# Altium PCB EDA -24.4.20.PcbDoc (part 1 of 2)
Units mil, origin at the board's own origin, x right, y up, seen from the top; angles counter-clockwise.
Board outline 1259.84 x 1062.87 mil, 4 copper layers (Top1, Gnd2, Signal3, Bottom4), stack 30.634 mil thick; 95 components, 111 nets, 499 pads, 259 vias.
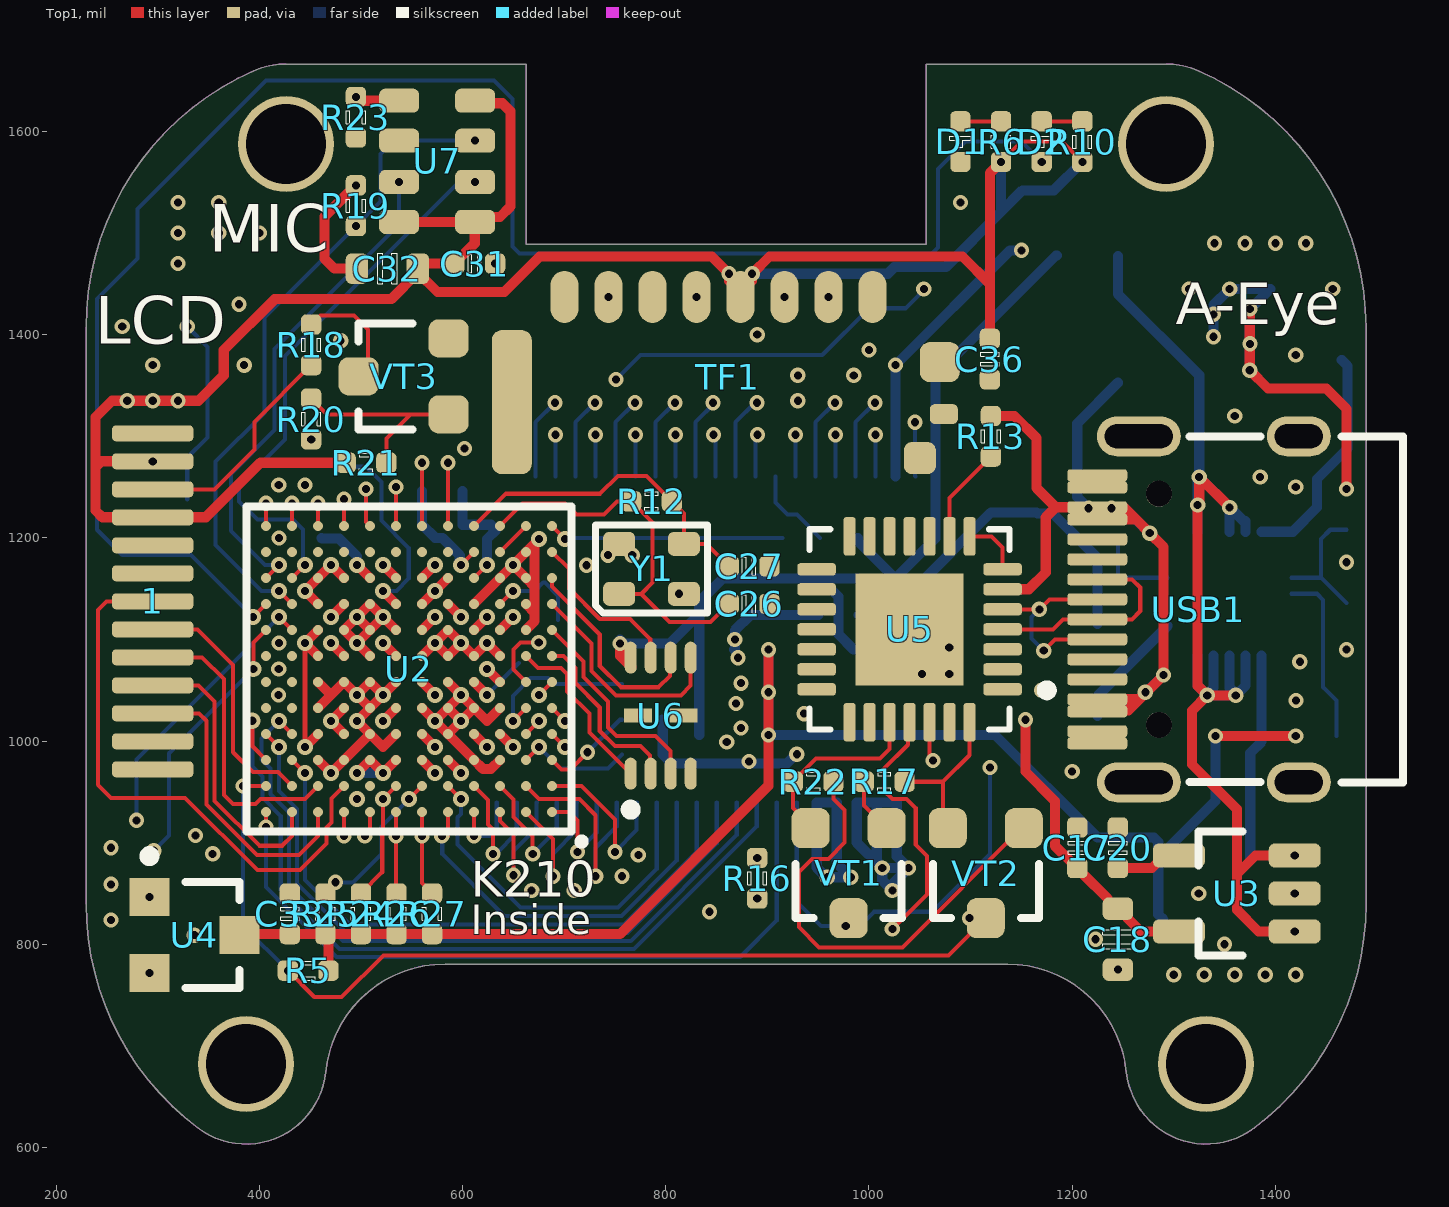
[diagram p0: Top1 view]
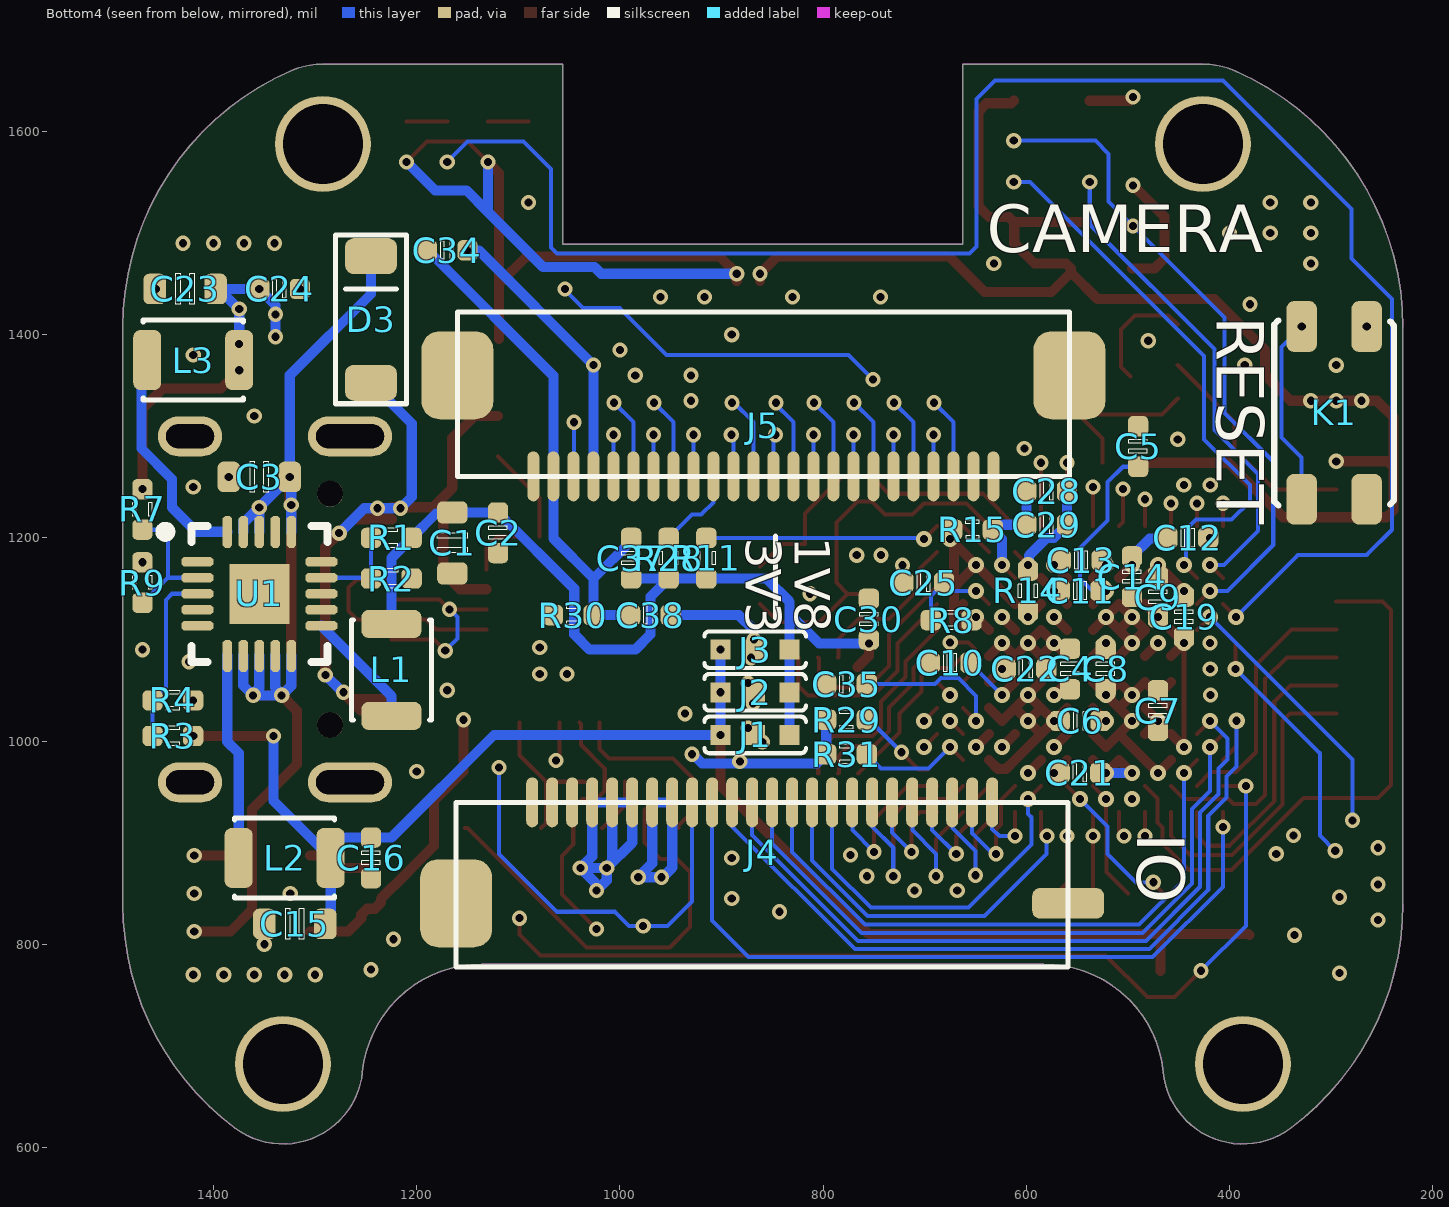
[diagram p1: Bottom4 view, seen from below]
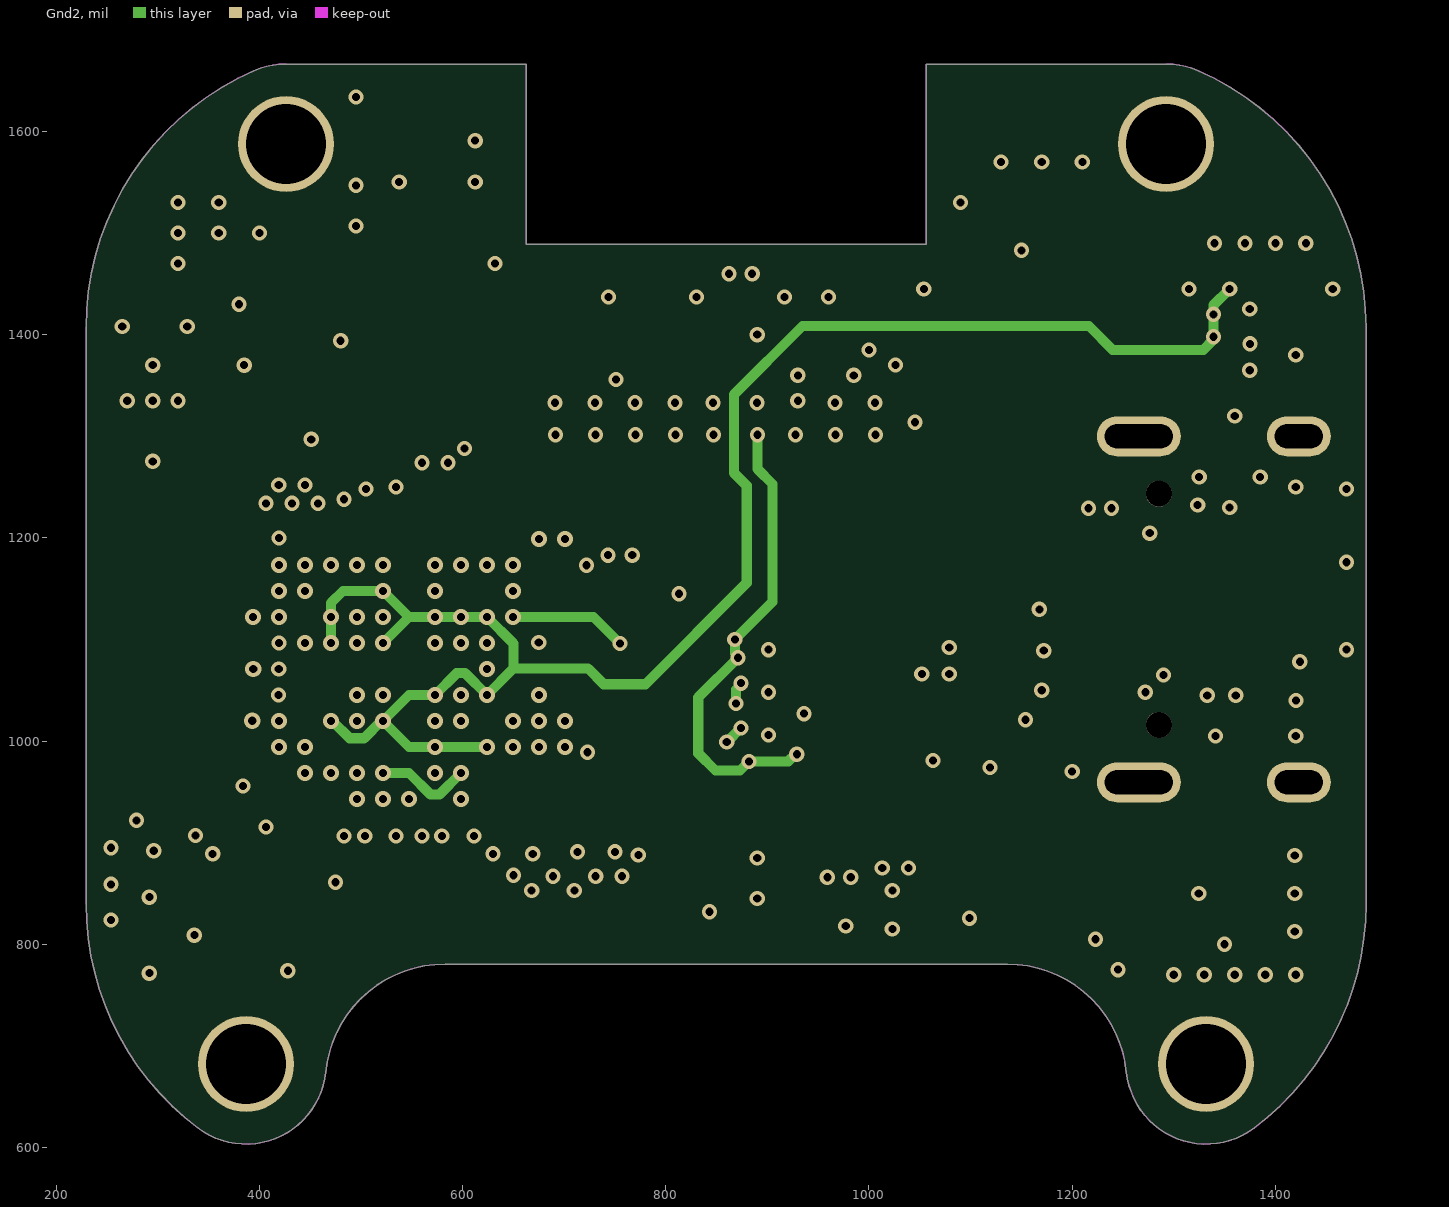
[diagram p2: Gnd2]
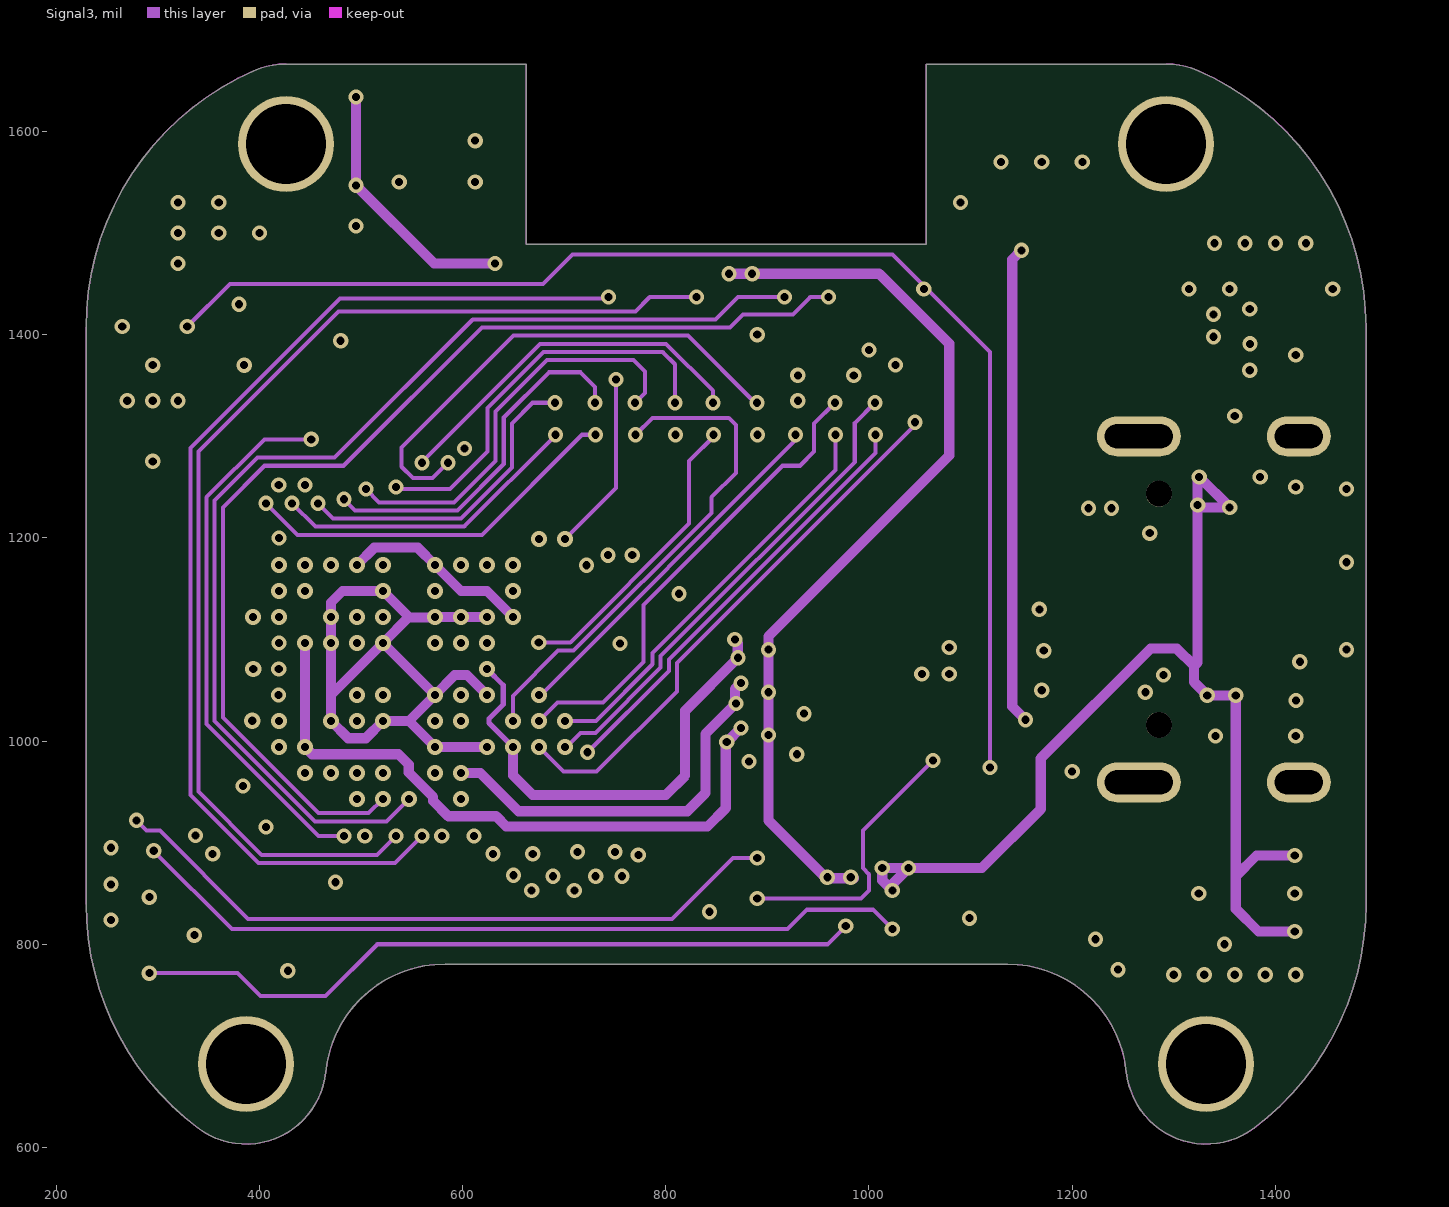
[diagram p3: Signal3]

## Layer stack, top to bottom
Top Solder: solder mask 0.4, Solder Resist, Dk 3.5
Top1: signal copper 1.4
Dielectric1: core 10, FR-4, Dk 4.2
Gnd2: signal copper 1.417
Dielectric3: core 10, Dk 4.2
Signal3: signal copper 1.417
Dielectric2: prepreg 5, Dk 4.2
Bottom4: signal copper 1.4
Bottom Solder: solder mask 0.4, Solder Resist, Dk 3.5

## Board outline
339.65,619.1 ccw(c386.9,682.09) 465.24,674.22 cw(c582.76,662.41) 582.76,780.52 1135.92,780.52 cw(c1135.92,662.41) 1253.43,674.22 ccw(c1331.78,682.09) 1379.02,619.1 ccw(c1213.67,839.57) 1489.26,839.57 1489.26,1407.19 ccw(c1213.67,1407.19) 1323.9,1659.77 ccw(c1292.41,1587.61) 1292.41,1666.35 1056.19,1666.35 1056.19,1489.18 662.49,1489.18 662.49,1666.35 426.27,1666.35 ccw(c426.27,1587.61) 394.77,1659.77 ccw(c505.01,1407.19) 229.42,1407.19 229.42,839.57 ccw(c505.01,839.57)

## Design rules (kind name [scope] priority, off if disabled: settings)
AssemblyTestPointUsage [All] p0: scope1count=1 scope1_0_kind=Board scope1_0_value=Board scope2count=1 scope2_0_kind=Board scope2_0_value=Board commentlength=0
AssemblyTestpoint [All] p0: scope1count=1 scope1_0_kind=Board scope1_0_value=Board scope2count=1 scope2_0_kind=Board scope2_0_value=Board commentlength=0
Clearance Solder_Clearance [All] p0: scope1count=1 scope1_0_kind=Layer scope1_0_value=TOP scope2count=1 scope2_0_kind=Layer scope2_0_value=TOP commentlength=0 gap=4
Clearance [All] p0: scope1count=1 scope1_0_kind=Board scope1_0_value=Board scope2count=1 scope2_0_kind=Board scope2_0_value=Board commentlength=0 gap=4
Clearance Solder_Clearance [OnLayer('Top Solder') vs OnLayer('Top Solder')] p1: gap=4 ignorepadtopadclearanceinfootprint=FALSE except(0: Arc-Hole Track-Hole SMDPad-Hole THPad-Hole Via-Hole Fill-Hole Poly-Hole Region-Hole Text-Hole)
Clearance [All] p2: gap=4 ignorepadtopadclearanceinfootprint=FALSE except(0: Arc-Hole Track-Hole SMDPad-Hole THPad-Hole Via-Hole Fill-Hole Poly-Hole Region-Hole Text-Hole)
ComponentClearance [All] p0: scope1count=1 scope1_0_kind=Board scope1_0_value=Board scope2count=1 scope2_0_kind=Board scope2_0_value=Board commentlength=0 gap=0 collisioncheckmode=3
ComponentClearance [All] p1: gap=0 collisioncheckmode=3 verticalgap=0 showdistances=FALSE
DiffPairsRouting [All] p0: scope1count=1 scope1_0_kind=Board scope1_0_value=Board scope2count=1 scope2_0_kind=Board scope2_0_value=Board commentlength=0
DiffPairsRouting [All] p1: maxlimit=9 minlimit=9 mostfreqgap=9 toplayer_minwidth=15 toplayer_maxwidth=15 toplayer_prefwidth=15 midlayer1_minwidth=15 midlayer1_maxwidth=15 midlayer1_prefwidth=15 midlayer2_minwidth=15 midlayer2_maxwidth=15 midlayer2_prefwidth=15 bottomlayer_minwidth=15 bottomlayer_maxwidth=15 bottomlayer_prefwidth=15 maxuncoupledlength=500
FabricationTestPointUsage [All] p0: scope1count=1 scope1_0_kind=Board scope1_0_value=Board scope2count=1 scope2_0_kind=Board scope2_0_value=Board commentlength=0 valid=0 allowmultiple=FALSE
FabricationTestpoint [All] p0: scope1count=1 scope1_0_kind=Board scope1_0_value=Board scope2count=1 scope2_0_kind=Board scope2_0_value=Board commentlength=0 side=3 testpointundercomponent=TRUE minsize=40 maxsize=100 preferedsize=60 minholesize=0 maxholesize=40 preferedholesize=32 testpointgrid=1
FanoutControl Fanout_BGA [All] p0: scope1count=1 scope1_0_kind=Board scope1_0_value=Board scope2count=1 scope2_0_kind=Board scope2_0_value=Board commentlength=26 // Fanout_BGA (Default Rule)
FanoutControl Fanout_LCC [All] p0 off: scope1count=1 scope1_0_kind=Board scope1_0_value=Board scope2count=1 scope2_0_kind=Board scope2_0_value=Board commentlength=69 // Protel DXP Scope 1 Expression Was: IsLCC   Fanout_LCC (Default Rule)
FanoutControl Fanout_SOIC [All] p0 off: scope1count=1 scope1_0_kind=Board scope1_0_value=Board scope2count=1 scope2_0_kind=Board scope2_0_value=Board commentlength=71 // Protel DXP Scope 1 Expression Was: IsSOIC   Fanout_SOIC (Default Rule)
FanoutControl Fanout_Small [All] p0 off: scope1count=1 scope1_0_kind=Board scope1_0_value=Board scope2count=1 scope2_0_kind=Board scope2_0_value=Board commentlength=84 // Protel DXP Scope 1 Expression Was: (CompPinCount < 5)   Fanout_Small (Default Rule)
FanoutControl Fanout_Default [All] p0: scope1count=1 scope1_0_kind=Board scope1_0_value=Board scope2count=1 scope2_0_kind=Board scope2_0_value=Board commentlength=30 // Fanout_Default (Default Rule)
FanoutControl Fanout_BGA [All] p1: bgadir=Out bgaviamode=Centered fanoutstyle=Auto fanoutdirection=Alternating viagrid=1 // Fanout_BGA (Default Rule)
Height [All] p0: scope1count=1 scope1_0_kind=Board scope1_0_value=Board scope2count=1 scope2_0_kind=Board scope2_0_value=Board commentlength=0
HoleSize [All] p0: scope1count=1 scope1_0_kind=Board scope1_0_value=Board scope2count=1 scope2_0_kind=Board scope2_0_value=Board commentlength=0 absolutevalues=TRUE maxlimit=10000 minlimit=8 maxpercent=80.000 minpercent=20.000
HoleSize [All] p1: absolutevalues=TRUE maxlimit=10000 minlimit=8 maxpercent=80.000 minpercent=20.000
HoleToHoleClearance [All] p0: scope1count=1 scope1_0_kind=Board scope1_0_value=Board scope2count=1 scope2_0_kind=Board scope2_0_value=Board commentlength=0
LayerPairs [All] p0: scope1count=1 scope1_0_kind=Board scope1_0_value=Board scope2count=1 scope2_0_kind=Board scope2_0_value=Board commentlength=0 enforce=TRUE
MinimumSolderMaskSliver [All] p0 off: scope1count=1 scope1_0_kind=Board scope1_0_value=Board scope2count=1 scope2_0_kind=Board scope2_0_value=Board commentlength=0
MinimumSolderMaskSliver [All] p1 off: minsoldermaskwidth=2
NetAntennae [All] p0: scope1count=1 scope1_0_kind=Board scope1_0_value=Board scope2count=1 scope2_0_kind=Board scope2_0_value=Board commentlength=0
PasteMaskExpansion [All] p0: scope1count=1 scope1_0_kind=Board scope1_0_value=Board scope2count=1 scope2_0_kind=Board scope2_0_value=Board commentlength=0 expansion=0
PlaneClearance [All] p0: scope1count=1 scope1_0_kind=Board scope1_0_value=Board scope2count=1 scope2_0_kind=Board scope2_0_value=Board commentlength=0 clearance=8
PlaneClearance [All] p1: clearance=8
PlaneConnect [All] p0: scope1count=1 scope1_0_kind=Board scope1_0_value=Board scope2count=1 scope2_0_kind=Board scope2_0_value=Board commentlength=0 planeconnectstyle=Direct reliefexpansion=20 reliefentries=4 reliefconductorwidth=10 reliefairgap=10
PlaneConnect [All] p1: planeconnectstyle=Direct reliefexpansion=20 reliefentries=4 reliefconductorwidth=10 reliefairgap=10
PolygonConnect [All] p0: scope1count=1 scope1_0_kind=Board scope1_0_value=Board scope2count=1 scope2_0_kind=Board scope2_0_value=Board commentlength=0 connectstyle=Direct reliefconductorwidth=10 reliefentries=4 polygonreliefangle="90 Angle"
PolygonConnect [All] p1: connectstyle=Direct reliefconductorwidth=10 reliefentries=4 polygonreliefangle="90 Angle" airgapwidth=10
RoutingCorners [All] p0: scope1count=1 scope1_0_kind=Board scope1_0_value=Board scope2count=1 scope2_0_kind=Board scope2_0_value=Board commentlength=0 cornerstyle=45-Degree minsetback=100 maxsetback=100
RoutingLayers [All] p0: scope1count=1 scope1_0_kind=Board scope1_0_value=Board scope2count=1 scope2_0_kind=Board scope2_0_value=Board commentlength=0 top layer=Automatic mid layer 1=Automatic mid layer 2=Automatic bottom layer=Automatic
RoutingPriority [All] p0: scope1count=1 scope1_0_kind=Board scope1_0_value=Board scope2count=1 scope2_0_kind=Board scope2_0_value=Board commentlength=0
RoutingTopology [All] p0: scope1count=1 scope1_0_kind=Board scope1_0_value=Board scope2count=1 scope2_0_kind=Board scope2_0_value=Board commentlength=0 topology=Shortest
RoutingVias [All] p0: scope1count=1 scope1_0_kind=Board scope1_0_value=Board scope2count=1 scope2_0_kind=Board scope2_0_value=Board commentlength=0 holewidth=8 width=16 viastyle="Through Hole" minholewidth=6 minwidth=12 maxholewidth=28 maxwidth=50
RoutingVias [All] p1: holewidth=8 width=16 viastyle="Through Hole" minholewidth=6 minwidth=12 maxholewidth=28 maxwidth=50
ShortCircuit [All] p0: scope1count=1 scope1_0_kind=Board scope1_0_value=Board scope2count=1 scope2_0_kind=Board scope2_0_value=Board commentlength=0 allowed=FALSE
SilkToBoardRegionClearance [All] p0: scope1count=1 scope1_0_kind=Board scope1_0_value=Board scope2count=1 scope2_0_kind=Board scope2_0_value=Board commentlength=0
SilkToSilkClearance [All] p0: scope1count=1 scope1_0_kind=Board scope1_0_value=Board scope2count=1 scope2_0_kind=Board scope2_0_value=Board commentlength=0
SilkToSilkClearance [All] p1: silktosilkclearance=0
SilkToSolderMaskClearance [All] p0 off: scope1count=1 scope1_0_kind=Board scope1_0_value=Board scope2count=1 scope2_0_kind=Board scope2_0_value=Board commentlength=44 // Protel DXP Scope 1 Expression Was: IsPad
SilkToSolderMaskClearance [IsPad] p1: minsilkscreentomaskgap=0 clearancetoexposedcopper=TRUE
SolderMaskExpansion [All] p0: scope1count=1 scope1_0_kind=Board scope1_0_value=Board scope2count=1 scope2_0_kind=Board scope2_0_value=Board commentlength=0 expansion=3
SolderMaskExpansion [All] p1: expansion=3 istentingtop=FALSE
UnRoutedNet [All] p0: scope1count=1 scope1_0_kind=Board scope1_0_value=Board scope2count=1 scope2_0_kind=Board scope2_0_value=Board commentlength=0
UnpouredPolygon [All] p0: scope1count=1 scope1_0_kind=Board scope1_0_value=Board scope2count=1 scope2_0_kind=Board scope2_0_value=Board commentlength=0
Width Width_Solder [All] p0: scope1count=1 scope1_0_kind=Layer scope1_0_value=TOP scope2count=1 scope2_0_kind=Board scope2_0_value=Board commentlength=0 maxlimit=10000 minlimit=0.1 preferedwidth=10
Width VCC [All] p0 off: scope1count=1 scope1_0_kind=Board scope1_0_value=Board scope2count=1 scope2_0_kind=Board scope2_0_value=Board commentlength=137 maxlimit=50 minlimit=4 preferedwidth=10 // Protel DXP Scope 1 Expression Was: (InNetClass('VCC-0V9') OR InNetClass('VCC-1V8') OR InNetClass('VCC-2V5') OR InNetClass('VCC-3V3'))
Width GND [All] p0 off: scope1count=1 scope1_0_kind=Board scope1_0_value=Board scope2count=1 scope2_0_kind=Board scope2_0_value=Board commentlength=70 maxlimit=50 minlimit=4 preferedwidth=10 // Protel DXP Scope 1 Expression Was: (InNet('AGND') OR InNet('GND'))
Width [All] p0: scope1count=1 scope1_0_kind=Board scope1_0_value=Board scope2count=1 scope2_0_kind=Board scope2_0_value=Board commentlength=0 maxlimit=10000 minlimit=4 preferedwidth=4
Width Width_Solder [OnLayer('Top Solder')] p1: maxlimit=10000 minlimit=0.1 preferedwidth=10
Width GND [(InNet('AGND') OR InNet('GND'))] p2: maxlimit=50 minlimit=4 preferedwidth=10
Width VCC [(InNetClass('VCC-0V9') OR InNetClass('VCC-1V8') OR InNetClass('VCC-2V5') OR InNetClass('VCC-3V3'))] p3: maxlimit=50 minlimit=4 preferedwidth=10
Width [All] p4: maxlimit=10000 minlimit=4 preferedwidth=4
21 further rules are at their usual default settings.

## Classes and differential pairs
net class CAMERA: DVP_HSYNC DVP_PCLK DVP_PWDN DVP_RST DVP_SCL DVP_SDA DVP_VSYNC DVP_XCLK DVP_Y2 DVP_Y3 DVP_Y4 DVP_Y5 DVP_Y6 DVP_Y7 DVP_Y8 DVP_Y9
net class EXT-IO: IO_6 IO_7 IO_8 IO_9 IO_10 IO_11 IO_12 IO_13 IO_14 IO_15 IO_17 IO_24 IO_25 IO_36 IO_37 IO_38 IO_39
net class VCC-3V3: VCC_3V3
net class VCC-0V9: VCC_0V9
net class VCC-2V5: VCC_2V5
net class VCC-1V8: VCC_1V8
net class FLASH: NetU2_G1 NetU2_G2 NetU2_H1 NetU2_J1 NetU2_K1 NetU2_L1

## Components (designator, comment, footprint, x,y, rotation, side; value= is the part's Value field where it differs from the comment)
1 "LCD-240x135" LCD-240x135 295,1137.56 r90 top locked
C1 "10uF" 0603-CAP 1165,1195 r90 bottom
C2 "0.1uF" CAP_0402 1120,1205 r270 bottom
C3 "10uF" 0603-CAP 1355,1260 r180 bottom
C4 "1uF" CAP_0402 557,1071 r270 bottom
C5 "1uF" CAP_0402 490,1290 r270 bottom
C6 "0.1uF" CAP_0402 547,1019.84 r180 bottom
C7 "0.1uF" CAP_0402 470.43,1030 r270 bottom
C8 "0.1uF" CAP_0402 522,1071 r90 bottom
C9 "0.1uF" CAP_0402 470.43,1141.8 r270 bottom
C10 "0.1uF" CAP_0402 675,1077 r180 bottom
C11 "0.1uF" CAP_0402 547,1148 r180 bottom
C12 "1uF" CAP_0402 441,1200 r0 bottom
C13 "1uF" CAP_0402 546,1178 r0 bottom
C14 "0.1uF" CAP_0402 496.02,1161.8 r90 bottom
C15 "10uF" 0603-CAP 1320,820 r180 bottom
C16 "0.1uF" CAP_0402 1245,885 r270 bottom
C17 "0.1uF" CAP_0402 1205,895 r270 top
C18 "10uF" 0603-CAP 1245,805 r90 top
C19 "0.1uF" CAP_0402 444.84,1122.21 r90 bottom
C20 "10nF" CAP_0402 1245,895 r270 top
C21 "0.1uF" CAP_0402 547.21,968.66 r0 bottom
C22 "0.1uF" CAP_0402 600.39,1071.02 r180 bottom
C23 "10uF" 0603-CAP 1428,1445 r180 bottom
C24 "0.1uF" CAP_0402 1335,1445 r180 bottom
C25 "0.1uF" CAP_0402 701,1156 r0 bottom
C26 "10pF" CAP_0402 882,1135 r0 top
C27 "10pF" CAP_0402 882,1172 r0 top
C28 "0.1uF" CAP_0402 580,1246 r180 bottom
C29 "1uF" CAP_0402 580,1213 r180 bottom
C30 "0.1uF" CAP_0402 755,1120 r90 bottom
C31 "0.1uF" CAP_0402 612,1470 r180 top
C32 "10uF" 0603-CAP 526,1465 r180 top
C33 "1uF" CAP_0402 430,830 r90 top
C34 "0.1uF" CAP_0402 1170,1483 r180 bottom
C35 "15pF" CAP_0402 777,1056 r0 bottom
C36 "0.1uF" CAP_0402 1119,1376 r270 top
C37 "0.1uF" CAP_0402 989,1180 r270 bottom
C38 "0.1uF" CAP_0402 970,1124 r180 bottom
D1 "color?" LED_0402_RED 1090,1590 r270 top
D2 "color?" LED_0402_RED 1170,1590 r270 top
D3 "二极管-5819W" SOD-123 1245,1415 r90 bottom
J1 "选择跳线" jumper-3 867,1006 r180 bottom
J2 "选择跳线" jumper-3 867,1048 r180 bottom
J3 "选择跳线" jumper-3 867,1090 r180 bottom
J4 "0.5S_A_24PWB" FPC-24P#1 860,890 r180 bottom locked
J5 "0.5S_A_24PWB" FPC-24P#2 858.82,1310.29 r0 bottom locked
K1 "TACT 4P" BUTTONTACT_3.5*3.55_90 297,1323 r270 bottom
L1 "2.2uH" 2520-L 1225,1070 r90 bottom
L2 "2.2uH" 2520-L 1330,885 r180 bottom
L3 "2.2uH" 2520-L 1420,1375 r180 bottom
R1 "150K" RES_0402 1225,1200 r180 bottom
R2 "100K" RES_0402 1225,1160 r0 bottom
R3 "510K" RES_0402 1440,1005 r180 bottom
R4 "110K" RES_0402 1440,1040 r0 bottom
R5 "10K" RES_0402 448,774 r0 top
R6 "1K" RES_0402 1130,1590 r90 top
R7 "62K" RES_0402 1470,1228 r90 bottom
R8 "0R" RES_0402 674,1119 r0 bottom
R9 "100K" RES_0402 1470,1156 r270 bottom
R10 "1K" RES_0402 1210,1590 r90 top
R11 "10K" RES_0402 915,1180 r270 bottom
R12 "1M" RES_0402 786,1236 r180 top
R13 "10K" RES_0402 1120,1300 r270 top
R14 "0R" RES_0402 598.39,1147.8 r270 bottom
R15 "0R" RES_0402 653,1208 r180 bottom
R16 "200R" RES_0402 890,865 r270 top
R17 "12K" RES_0402 1015,960 r180 top
R18 "10R" RES_0402 451,1390 r270 top
R19 "100K" RES_0402 495,1527 r90 top
R20 "1K" RES_0402 451,1317 r270 top
R21 "10K" RES_0402 505,1274 r180 top
R22 "12K" RES_0402 945,960 r0 top
R23 "0R" RES_0402 495,1614 r270 top
R24 "10K" RES_0402 500,830 r270 top
R25 "10K" RES_0402 465,830 r270 top
R26 "10K" RES_0402 535,830 r270 top
R27 "10K" RES_0402 570,830 r270 top
R28 "10R" RES_0402 952,1180 r270 bottom
R29 "10K" RES_0402 777,1021 r0 bottom
R30 "0R" RES_0402 1046,1124 r0 bottom
R31 "10K" RES_0402 777,987 r0 bottom
TF1 "TF" "TF-SOCKET - short" 865,1310 r270 top locked
U1 "EA3036" QFN20_40P300X300X80_HS-21N 1355,1145 r180 bottom
U2 "K210" BGA144C65P12X12_800X800X95 547.2,1071.02 r180 top locked
U3 "LP2992 2V5" SOT23-5 1360,850 r180 top
U4 "SGM803[NC]" SOT23-3 336,809 r270 top
U5 "CP2102" QFN-28 1040,1110 r180 top
U6 "W25Xxx" USON-8N 795,1025 r90 top
U7 "MSM261S4030H0" MSM-MIC 575,1570 r180 top
USB1 "Type-C" Type-C-TOP 1323.9,1129.69 r0 top locked
VT1 "S8050" SMT_TRIODE_NPN 980,870 r180 top
VT2 "S8050" SMT_TRIODE_NPN 1115,870 r180 top
VT3 "S8050" SMT_TRIODE_NPN 542,1359 r90 top
Y1 "26MHz" 晶振2520 785.98,1169.45 r0 top

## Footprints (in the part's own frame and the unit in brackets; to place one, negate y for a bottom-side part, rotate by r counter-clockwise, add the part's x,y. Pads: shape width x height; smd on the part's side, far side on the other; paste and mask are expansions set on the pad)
0603-CAP [mil]
  rrect50% 22x30 smd: 1(-30,0) 2(30,0)
  silkscreen extent -10,-15 10,15
2520-L [mm]
  rrect50% 0.7x1.5 smd: 1(-1.15,0) 2(1.15,0)
  silkscreen extent -1.25,-1 1.25,1
BGA144C65P12X12_800X800X95 [mm] "BGA, 144-Leads, Body 8.00x8.00mmx0.95mm, Pitch 0.65mm"
  round 0.25 smd mask+0: A1(-3.575,3.575) A2(-2.925,3.575) A3(-2.275,3.575) A4(-1.625,3.575) A5(-0.975,3.575) A6(-0.325,3.575) A7(0.325,3.575) A8(0.975,3.575) A9(1.625,3.575) A10(2.275,3.575) A11(2.925,3.575) A12(3.575,3.575) B1(-3.575,2.925) B2(-2.925,2.925) B3(-2.275,2.925) B4(-1.625,2.925) B5(-0.975,2.925) B6(-0.325,2.925) B7(0.325,2.925) B8(0.975,2.925) B9(1.625,2.925) B10(2.275,2.925) B11(2.925,2.925) B12(3.575,2.925) C1(-3.575,2.275) C2(-2.925,2.275) C3(-2.275,2.275) C4(-1.625,2.275) C5(-0.975,2.275) C6(-0.325,2.275) C7(0.325,2.275) C8(0.975,2.275) C9(1.625,2.275) C10(2.275,2.275) C11(2.925,2.275) C12(3.575,2.275) D1(-3.575,1.625) D2(-2.925,1.625) D3(-2.275,1.625) D4(-1.625,1.625) D5(-0.975,1.625) D6(-0.325,1.625) D7(0.325,1.625) D8(0.975,1.625) D9(1.625,1.625) D10(2.275,1.625) D11(2.925,1.625) D12(3.575,1.625) E1(-3.575,0.975) E2(-2.925,0.975) E3(-2.275,0.975) E4(-1.625,0.975) E5(-0.975,0.975) E6(-0.325,0.975) E7(0.325,0.975) E8(0.975,0.975) E9(1.625,0.975) E10(2.275,0.975) E11(2.925,0.975) E12(3.575,0.975) F1(-3.575,0.325) F2(-2.925,0.325) F3(-2.275,0.325) F4(-1.625,0.325) F5(-0.975,0.325) F6(-0.325,0.325) F7(0.325,0.325) F8(0.975,0.325) F9(1.625,0.325) F10(2.275,0.325) F11(2.925,0.325) F12(3.575,0.325) G1(-3.575,-0.325) G2(-2.925,-0.325) G3(-2.275,-0.325) G4(-1.625,-0.325) G5(-0.975,-0.325) G6(-0.325,-0.325) G7(0.325,-0.325) G8(0.975,-0.325) G9(1.625,-0.325) G10(2.275,-0.325) G11(2.925,-0.325) G12(3.575,-0.325) H1(-3.575,-0.975) H2(-2.925,-0.975) H3(-2.275,-0.975) H4(-1.625,-0.975) H5(-0.975,-0.975) H6(-0.325,-0.975) H7(0.325,-0.975) H8(0.975,-0.975) H9(1.625,-0.975) H10(2.275,-0.975) H11(2.925,-0.975) H12(3.575,-0.975) J1(-3.575,-1.625) J2(-2.925,-1.625) J3(-2.275,-1.625) J4(-1.625,-1.625) J5(-0.975,-1.625) J6(-0.325,-1.625) J7(0.325,-1.625) J8(0.975,-1.625) J9(1.625,-1.625) J10(2.275,-1.625) J11(2.925,-1.625) J12(3.575,-1.625) K1(-3.575,-2.275) K2(-2.925,-2.275) K3(-2.275,-2.275) K4(-1.625,-2.275) K5(-0.975,-2.275) K6(-0.325,-2.275) K7(0.325,-2.275) K8(0.975,-2.275) K9(1.625,-2.275) K10(2.275,-2.275) K11(2.925,-2.275) K12(3.575,-2.275) L1(-3.575,-2.925) L2(-2.925,-2.925) L3(-2.275,-2.925) L4(-1.625,-2.925) L5(-0.975,-2.925) L6(-0.325,-2.925) L7(0.325,-2.925) L8(0.975,-2.925) L9(1.625,-2.925) L10(2.275,-2.925) L11(2.925,-2.925) L12(3.575,-2.925) M1(-3.575,-3.575) M2(-2.925,-3.575) M3(-2.275,-3.575) M4(-1.625,-3.575) M5(-0.975,-3.575) M6(-0.325,-3.575) M7(0.325,-3.575) M8(0.975,-3.575) M9(1.625,-3.575) M10(2.275,-3.575) M11(2.925,-3.575) M12(3.575,-3.575)
  silkscreen extent -4.39,-4.06 4.06,4.39
BUTTONTACT_3.5*3.55_90 [mil]
  rrect50% 50x30 smd: 1(-85,32) 2(-85,-32) 3(85,32) 4(85,-32)
  silkscreen extent -91,-59 91,59
CAP_0402 [mil]
  rrect50% 20x20 smd: 1(-20,0) 2(20,0)
  silkscreen extent -7,-9 7,9
FPC-24P#1 [mm]
  oval 0.3x1.25 smd: 1(5.75,1.263) 2(5.25,1.263) 3(4.75,1.263) 4(4.25,1.263) 5(3.75,1.263) 6(3.25,1.263) 7(2.75,1.263) 8(2.25,1.263) 9(1.75,1.263) 10(1.25,1.263) 11(0.75,1.263) 12(0.25,1.263) 13(-0.25,1.263) 14(-0.75,1.263) 15(-1.25,1.263) 16(-1.75,1.263) 17(-2.25,1.263) 18(-2.75,1.263) 19(-3.25,1.263) 20(-3.75,1.263) 21(-4.25,1.263) 22(-4.75,1.263) 23(-5.25,1.263) 24(-5.75,1.263)
  rrect50% 1.8x2.2 smd: ""(-7.65,-1.263)
  rrect50% 1.8x0.762 smd: ""(7.65,-1.263)
  silkscreen extent -7.65,-2.85 7.65,1.26
FPC-24P#2 [mm]
  oval 0.3x1.25 smd: 1(5.75,1.263) 2(5.25,1.263) 3(4.75,1.263) 4(4.25,1.263) 5(3.75,1.263) 6(3.25,1.263) 7(2.75,1.263) 8(2.25,1.263) 9(1.75,1.263) 10(1.25,1.263) 11(0.75,1.263) 12(0.25,1.263) 13(-0.25,1.263) 14(-0.75,1.263) 15(-1.25,1.263) 16(-1.75,1.263) 17(-2.25,1.263) 18(-2.75,1.263) 19(-3.25,1.263) 20(-3.75,1.263) 21(-4.25,1.263) 22(-4.75,1.263) 23(-5.25,1.263) 24(-5.75,1.263)
  rrect50% 1.8x2.2 smd: ""(-7.65,-1.263) ""(7.65,-1.263)
  silkscreen extent -7.65,-2.85 7.65,1.26
jumper-3 [mm]
  rect 0.5x0.5 smd: 1(-0.864,0) 2(0,0) 3(0.864,0)
  silkscreen extent -1.27,-0.46 1.27,0.46
LCD-240x135 [mm]
  rrect50% 0.4x2.032 smd: 1(-4.2,0) 2(-3.5,0) 3(-2.8,0) 4(-2.1,0) 5(-1.4,0) 6(-0.7,0) 7(0,0) 8(0.7,0) 9(1.4,0) 10(2.1,0) 11(2.8,0) 12(3.5,0) 13(4.2,0)
LED_0402_RED [mil]
  rrect50% 20x20 smd: 1(-20,0) 2(20,0)
  silkscreen extent -6,-11 6,10
MSM-MIC [mm]
  rrect50% 1x0.6 smd: 1(0.95,-1.532) 2(0.95,-0.532) 3(0.95,0.5) 4(0.95,1.5) 5(-0.95,1.5) 6(-0.95,0.5) 7(-0.95,-0.532) 8(-0.95,-1.532)
QFN20_40P300X300X80_HS-21N [mm] "QFN, 20-Leads, Body 3.00x3.00mm, Pitch 0.40mm, Thermal Pad 1.65x1.65mm, IPC Medium Density"
  oct 0.8x0.24 smd: 1(-1.55,0.8) 2(-1.55,0.4) 3(-1.55,0) 4(-1.55,-0.4) 5(-1.55,-0.8) 11(1.55,-0.8) 12(1.55,-0.4) 13(1.55,0) 14(1.55,0.4) 15(1.55,0.8)
  oct 0.24x0.8 smd: 6(-0.8,-1.55) 7(-0.4,-1.55) 8(0,-1.55) 9(0.4,-1.55) 10(0.8,-1.55) 16(0.8,1.55) 17(0.4,1.55) 18(0,1.55) 19(-0.4,1.55) 20(-0.8,1.55)
  rect 1.5x1.5 smd: 21(0,0)
  silkscreen extent -2.48,-1.7 1.7,1.7
QFN-28 [mil]
  rrect50% 38x12 smd mask+0: 1(-91.5,59.06) 2(-91.5,39.37) 3(-91.5,19.68) 4(-91.5,0) 5(-91.5,-19.69) 6(-91.5,-39.37) 7(-91.5,-59.06) 15(91.5,-59.06) 16(91.5,-39.37) 17(91.5,-19.69) 18(91.5,0) 19(91.5,19.68) 20(91.5,39.37) 21(91.5,59.06)
  rrect50% 12x38 smd mask+0: 8(-59.06,-91.5) 9(-39.37,-91.5) 10(-19.69,-91.5) 11(0,-91.5) 12(19.68,-91.5) 13(39.37,-91.5) 14(59.06,-91.5) 22(59.06,91.5) 23(39.37,91.5) 24(19.68,91.5) 25(0,91.5) 26(-19.69,91.5) 27(-39.37,91.5) 28(-59.06,91.5)
  rect 106.3x110.24 smd: 29(0,0)
  silkscreen extent -140,-99 99,99
RES_0402 [mil]
  rrect50% 20x20 smd: 1(-20,0) 2(20,0)
  silkscreen extent -7,-10 7,10
SMT_TRIODE_NPN [mm] "Surface mount NPN transistor, package SOT-23"
  rrect50% 0.95x1 smd: 1(-0.95,-1.125) 2(0.95,-1.125) 3(0,1.125)
  silkscreen extent -1.33,-0.22 1.32,1.13
SOD-123 [mm]
  rrect50% 0.9x1.3 smd: 1(-1.583,0) 2(1.583,0)
  silkscreen extent -2.11,-0.89 2.11,0.89
SOT23-3 [mm] "SOT-23; 3 Leads; Body 3.0 x 2.5 mm, inc. leads (LxW max)"
  rect 0.95x1 smd: 1(-0.95,-1.125) 2(0.95,-1.125) 3(0,1.125)
  silkscreen extent -2.1,-1.25 1.32,1.13
SOT23-5 [mm] "SOT23, 3-Leads, Body 3.1x3.0mm (max), Pitch 0.95mm, IPC Medium Density"
  rrect50% 1.3x0.6 smd: 1(-1.5,0.95) 2(-1.5,0) 3(-1.5,-0.95) 4(1.396,-0.95) 5(1.396,0.95)
  silkscreen extent -0.2,-1.55 0.9,1.55
"TF-SOCKET - short" [mm]
  oval 1.3x0.7 smd: 1(-3.231,3.518) 2(-3.231,2.418) 3(-3.231,1.318) 4(-3.231,0.218) 5(-3.231,-0.882) 6(-3.231,-1.982) 7(-3.231,-3.082) 8(-3.231,-4.182)
  rrect50% 0.8x0.8 smd: 9(0.8,4.7)
  rrect50% 0.5x0.7 smd: 10(-0.3,5.3)
  rrect50% 1x1 smd: ""(-1.6,5.2)
  rrect50% 3.6x1 smd: ""(-0.6,-5.5)
Type-C-TOP [mm]
  round 0.65 hole 0.65: 0(-0.98,-2.89) 0(-0.98,2.89)
  oval 1.6x1 hole 0.6 slot 1.2 at 0 deg: 1(2.52,4.325) 2(2.52,-4.325)
  oval 2.1x1 hole 0.6 slot 1.7 at 0 deg: 3(-1.48,-4.325) 4(-1.48,4.325)
  rrect50% 1.5x0.3 smd: A1(-2.52,-3.35) A4(-2.52,-2.55) A5(-2.52,-1.25) A6(-2.52,-0.25) A7(-2.52,0.25) A8(-2.52,1.25) A9(-2.52,2.55) A12(-2.52,3.35) B1(-2.52,3.05) B4(-2.52,2.25) B5(-2.52,1.75) B6(-2.52,0.75) B7(-2.52,-0.75) B8(-2.52,-1.75) B9(-2.52,-2.25) B12(-2.52,-3.05)
  silkscreen extent -0.22,-4.33 5.12,4.33
USON-8N [mm]
  oval 0.8x0.3 smd paste+0 mask+0: 1(-1.45,0.75) 2(-1.45,0.25) 3(-1.45,-0.25) 4(-1.45,-0.75) 5(1.45,-0.75) 6(1.45,-0.25) 7(1.45,0.25) 8(1.45,0.75)
  rect 0.35x0.7 smd paste+0 mask+0: GNDA(0,0.57) GNDB(0,-0.57)
  silkscreen extent -2.47,0.63 -2.23,0.87
晶振2520 [mm]
  rrect50% 0.8x0.6 smd: 1(-0.81,-0.625) 2(0.81,-0.625) 3(0.81,0.625) 4(-0.81,0.625)
  silkscreen extent -1.4,-1.1 1.4,1.1

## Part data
1: "显示屏"
C1 C3 C15 C18 C23 C32: library part 电容-0603, "Capacitor"
C2 C4 C5 C6 C7 C8 C9 C10 C11 C12 C13 C14 C16 C17 C19 C20 C21 C22 C24 C25 C26 C27 C28 C29 C30 C31 C33 C34 C35 C36 C37 C38: library part 电容-0402, "Capacitor"
D1 D2: library part LED_0402, "LED"
D3: library part 二极管-5, "40V"
J1 J2 J3: "Resistor"
J4: library part FPC24-0.5mm, "Header, 24-Pin"
J5: library part OV2640, "Header, 24-Pin"
K1: library part ButtonTACT, "Button"
L1 L2 L3: library part 电感-25, "磁珠"
R1 R2 R3 R4 R5 R6 R7 R8 R9 R10 R11 R12 R13 R14 R15 R16 R17 R18 R19 R20 R21 R22 R23 R24 R25 R26 R27 R28 R29 R30 R31: library part 电阻-0402, "Resistor"
TF1: library part TF卡?, "8脚自弹"
U1: "EA3036 is a 3CH power management IC for applications powered by one Li-Ion battery or a DC 5V adapter."
U2: "Canaan Kendryte K210 AI SoC"
U3: library part LP2992, "LDO"
U4: library part SGM803, "SGM803/SGM809/SGM810 / Microprocessor Supervisory / Circuit"
U5: "USBתTTL"
U6: library part W25XXX, "Serial flash memory with 4kB sectors and dual I/O SPI"
USB1: library part USB-Type-C-TOP
VT1 VT2 VT3: library part SMT_TRIODE_NPN, "Surface mount NPN transistor, package SOT-23"
Y1: library part 晶振-4, "2520无源"

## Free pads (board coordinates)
  round 94.49 hole 78.74: ""(386.9,682.09) ""(426.27,1587.61) ""(1292.41,1587.61) ""(1331.78,682.09)

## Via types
v1: diameter 15, hole 8, Top1 to Bottom4, tented both sides, 192 vias
v2: diameter 16, hole 8, Top1 to Bottom4, tented both sides, 67 vias

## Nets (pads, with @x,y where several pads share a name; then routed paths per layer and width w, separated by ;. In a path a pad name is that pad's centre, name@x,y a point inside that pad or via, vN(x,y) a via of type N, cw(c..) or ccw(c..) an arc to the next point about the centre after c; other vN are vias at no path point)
AGND: C34.1 C37.1 C38.1 J5.2 R30.1 | length 511.8
  Bottom4 w10: C37.1@989,1200 989,1197 1026,1160 ; C38.1@990,1124 R30.1@1026,1124 1026,1160 ; C34.1@1185,1478 1184,1478 1065.53,1359.53 J5.2@1065.53,1260.59 1065.53,1199.53 1026,1160
BOOT: R5.1 U2.B12 VT2.3 | length 945.9
  Top1 w4: v1(384,955.87) U2.B12@406.46,955.87 ; v1(428,774) 454,748 481,748 522,789 1078.29,789 1099,809.71 v1(1099,825.71)
  Bottom4 w4: v1(384,955.87) 384,818 v1(428,774)
CP_Rx: U2.H12 U5.25 | length 1291.3
  Top1 w4: v2(394,1071) 394,1096.95 U2.H12@406.46,1109.41 ; v1(1023,815) 1057,849 1057,887 1046,898 1046,934 1037,943 1023,943 1015,951 1015,973 1038.39,996.39 1038.39,1016.89 U5.25@1040,1018.5
  Signal3 w4: v1(296,892) 373,815 920,815 939,834 1004,834 v1(1023,815)
  Bottom4 w4: v1(296,892) 311,907 311,988 v2(394,1071)
CP_Tx: R16.1 U2.H11 | length 952.4
  Top1 w4: v2(419.25,1122.21) U2.H11@432.05,1109.41
  Signal3 w4: v1(279,922) 289,912 302,912 389,825 806,825 866,885 v1(890,885)
  Bottom4 w4: v1(279,922) 279,981.95 v2(419.25,1122.21)
DTR: R17.1 U5.28 VT2.2 | length 154.9
  Top1 w4: R17.1@1035,960 1073,960 ; VT2.2@1077.6,914.29 1073,918.89 1073,960 ; U5.28@1099.06,1018.5 1099.06,986.06 1073,960
DVP_HSYNC: J5.9 U2.F1 | length 420.8
  Top1 w4: v2(675.16,1045.43) U2.F1@687.95,1058.23
  Signal3 w4: v2(675.16,1045.43) 677.06,1045.43 927.73,1296.1 v1(927.73,1301.51)
  Bottom4 w4: J5.9@927.73,1260.59 v1(927.73,1301.51)
DVP_PCLK: C35.1 J5.17 U2.E2 | length 701.2
  Top1 w4: v2(649.57,1019.84) U2.E2@662.36,1032.64
  Signal3 w4: v2@649,1020.41 v2(649.57,1019.84) 649.57,1044.57 694,1089 709.31,1089 845,1224.69 845,1240 869,1264 869,1311 862,1318 786.74,1318 v1(770.25,1301.51)
  Bottom4 w4: v2(649.57,1019.84) 649.57,1044.57 667,1062 684,1062 690,1056 C35.1@757,1056 ; J5.17@770.25,1260.59 v1(770.25,1301.51)
DVP_PWDN: J5.8 U2.D2 | length 568.5
  Top1 w4: U2.D2@662.36,1007.05 v2(675.16,1019.84)
  Signal3 w4: v2(675.16,1019.84) 693.31,1038 738.06,1038 778,1077.94 778,1134 915,1271 932,1271 946,1285 946,1312.41 v1(966.59,1333)
  Bottom4 w4: J5.8@947.42,1260.59 947.42,1313.83 v1(966.59,1333)
DVP_RST: J5.6 U2.D1 | length 573.1
  Top1 w4: U2.D1@687.95,1007.05 v2(700.75,994.25)
  Signal3 w4: v2(700.75,994.25) 702.25,994.25 716,1008 730.69,1008 795,1072.31 795,1083.53 986,1274.53 986,1313.04 v1(1005.96,1333)
  Bottom4 w4: J5.6@986.79,1260.59 986.79,1313.83 v1(1005.96,1333)
DVP_SCL: J5.5 R29.1 U2.C1 | length 564.1
  Top1 w4: U2.C1@687.95,981.46 697.41,972 706,972 v1(723,989)
  Signal3 w4: v1(723,989) 803,1069 803,1080.22 1006.47,1283.69 v1(1006.47,1301.51)
  Bottom4 w4: v1(723,989) 755,1021 R29.1@757,1021 ; J5.5@1006.47,1260.59 v1(1006.47,1301.51)
DVP_SDA: J5.3 R31.1 U2.C2 | length 708.5
  Top1 w4: U2.C2@662.36,981.46 v2(675.16,994.25)
  Signal3 w4: v2(675.16,994.25) 699.41,970 732,970 811,1049 811,1076.9 1045.33,1311.23 v1(1045.33,1313.83)
  Bottom4 w4: v2(675.16,994.25) 696.41,973 743,973 R31.1@757,987 ; v1(1045.33,1313.83) 1045.33,1261.1 J5.3@1045.84,1260.59
DVP_VSYNC: J5.7 U2.E1 | length 468.9
  Top1 w4: U2.E1@687.95,1032.64 v2(700.75,1019.84)
  Signal3 w4: v2(700.75,1019.84) 731.21,1019.84 787,1075.63 787,1086.84 967.1,1266.94 v1(967.1,1301.51)
  Bottom4 w4: J5.7@967.1,1260.59 v1(967.1,1301.51)
DVP_XCLK: J5.13 U2.F2 | length 400.5
  Top1 w4: U2.F2@662.36,1058.23 650,1070.59 650,1090 657,1097 v1(675,1097)
  Signal3 w4: v1(675,1097) 706,1097 823,1214 823,1275.52 v1@848.99,1301.51
  Bottom4 w4: J5.13@848.99,1260.59 v1@848.99,1301.51
  other v1: 846.99,1301.51
DVP_Y2: J5.19 U2.M12 | length 441.2
  Top1 w4: U2.M12@406.46,1211.77 v1(406.46,1234)
  Signal3 w4: v1(406.46,1234) 437.46,1203 619,1203 717.51,1301.51 v1(730.88,1301.51)
  Bottom4 w4: J5.19@730.88,1260.59 v1(730.88,1301.51)
DVP_Y3: J5.21 U2.M11 | length 370
  Top1 w4: U2.M11@432.05,1211.77 v1(432.05,1234)
  Signal3 w4: v1(432.05,1234) 455.05,1211 601.63,1211 691.51,1300.88 v1(691.51,1301.51)
  Bottom4 w4: J5.21@691.51,1260.59 v1(691.51,1301.51)
DVP_Y4: J5.22 U2.M10 | length 414.8
  Top1 w4: U2.M10@457.64,1211.77 v1(457.64,1234)
  Signal3 w4: v1(457.64,1234) 472.64,1219 598.31,1219 648.51,1269.19 648.51,1312.51 669,1333 v1(691,1333)
  Bottom4 w4: J5.22@671.83,1260.59 671.83,1313.83 v1(691,1333)
DVP_Y5: J5.20 U2.M9 | length 463.4
  Top1 w4: U2.M9@483.23,1211.77 v1(483.23,1238)
  Signal3 w4: v1@483.23,1237.77 v1(483.23,1238) 494.23,1227 595,1227 640.51,1272.51 640.51,1318.51 685,1363 716,1363 730.37,1348.63 v1(730.37,1333)
  Bottom4 w4: J5.20@711.2,1260.59 711.2,1313.83 v1(730.37,1333)
DVP_Y6: J5.18 U2.M8 | length 519.2
  Top1 w4: v1@504.82,1243 504.82,1215.77 U2.M8@508.82,1211.77
  Signal3 w4: v1(504.82,1248) 517.82,1235 591.69,1235 632.51,1275.82 632.51,1324.51 683,1375 768.26,1375 779.37,1363.89 779.37,1342.63 v1(769.74,1333)
  Bottom4 w4: J5.18@750.57,1260.59 750.57,1313.83 v1(769.74,1333)
DVP_Y7: J5.16 U2.M7 | length 515.3
  Top1 w4: U2.M7@534.41,1211.77 v1@534.41,1248
  Signal3 w4: v1@534.41,1248 587.65,1248 624.51,1284.86 624.51,1327.82 679.69,1383 797,1383 809.11,1370.89 v1(809.11,1333)
  Bottom4 w4: J5.16@789.94,1260.59 789.94,1313.83 v1(809.11,1333)
  other v1: 534.41,1250
DVP_Y8: J5.14 U2.M6 | length 515.2
  Top1 w4: U2.M6@560,1211.77 v1(560,1274)
  Signal3 w4: v1@561,1274 561,1275.63 676.37,1391 800.31,1391 846.48,1344.83 v1@846.48,1335 ; v1@843.69,1337.79 v1@846.48,1335 ; v1(846.48,1333) v1@846.48,1335 ; v1@848.48,1333 v1@846.48,1335
  Bottom4 w4: J5.14@829.31,1260.59 829.31,1313.83 v1@848.48,1333
DVP_Y9: J5.12 U2.M5 | length 638.7
  Top1 w4: U2.M5@585.59,1211.77 v1(585.59,1274)
  Signal3 w4: v1(585.59,1274) 570.59,1259 551,1259 540,1270 540,1289 650,1399 821.85,1399 v1@887.85,1333
  Bottom4 w4: J5.12@868.68,1260.59 868.68,1313.83 v1@887.85,1333
  other v1: 889.85,1333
